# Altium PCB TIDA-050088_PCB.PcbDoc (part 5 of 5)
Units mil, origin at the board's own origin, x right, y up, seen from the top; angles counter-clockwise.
Board outline 8500 x 7000 mil, 8 copper layers (Top Layer, Layer 1 - GND, Signal Layer 2, Layer 3 - GND, Layer 4 - Power, Signal Layer 5, Layer 6 - GND, Bottom Layer), stack 61.6 mil thick; 537 components, 169 nets, 1427 pads, 1411 vias.
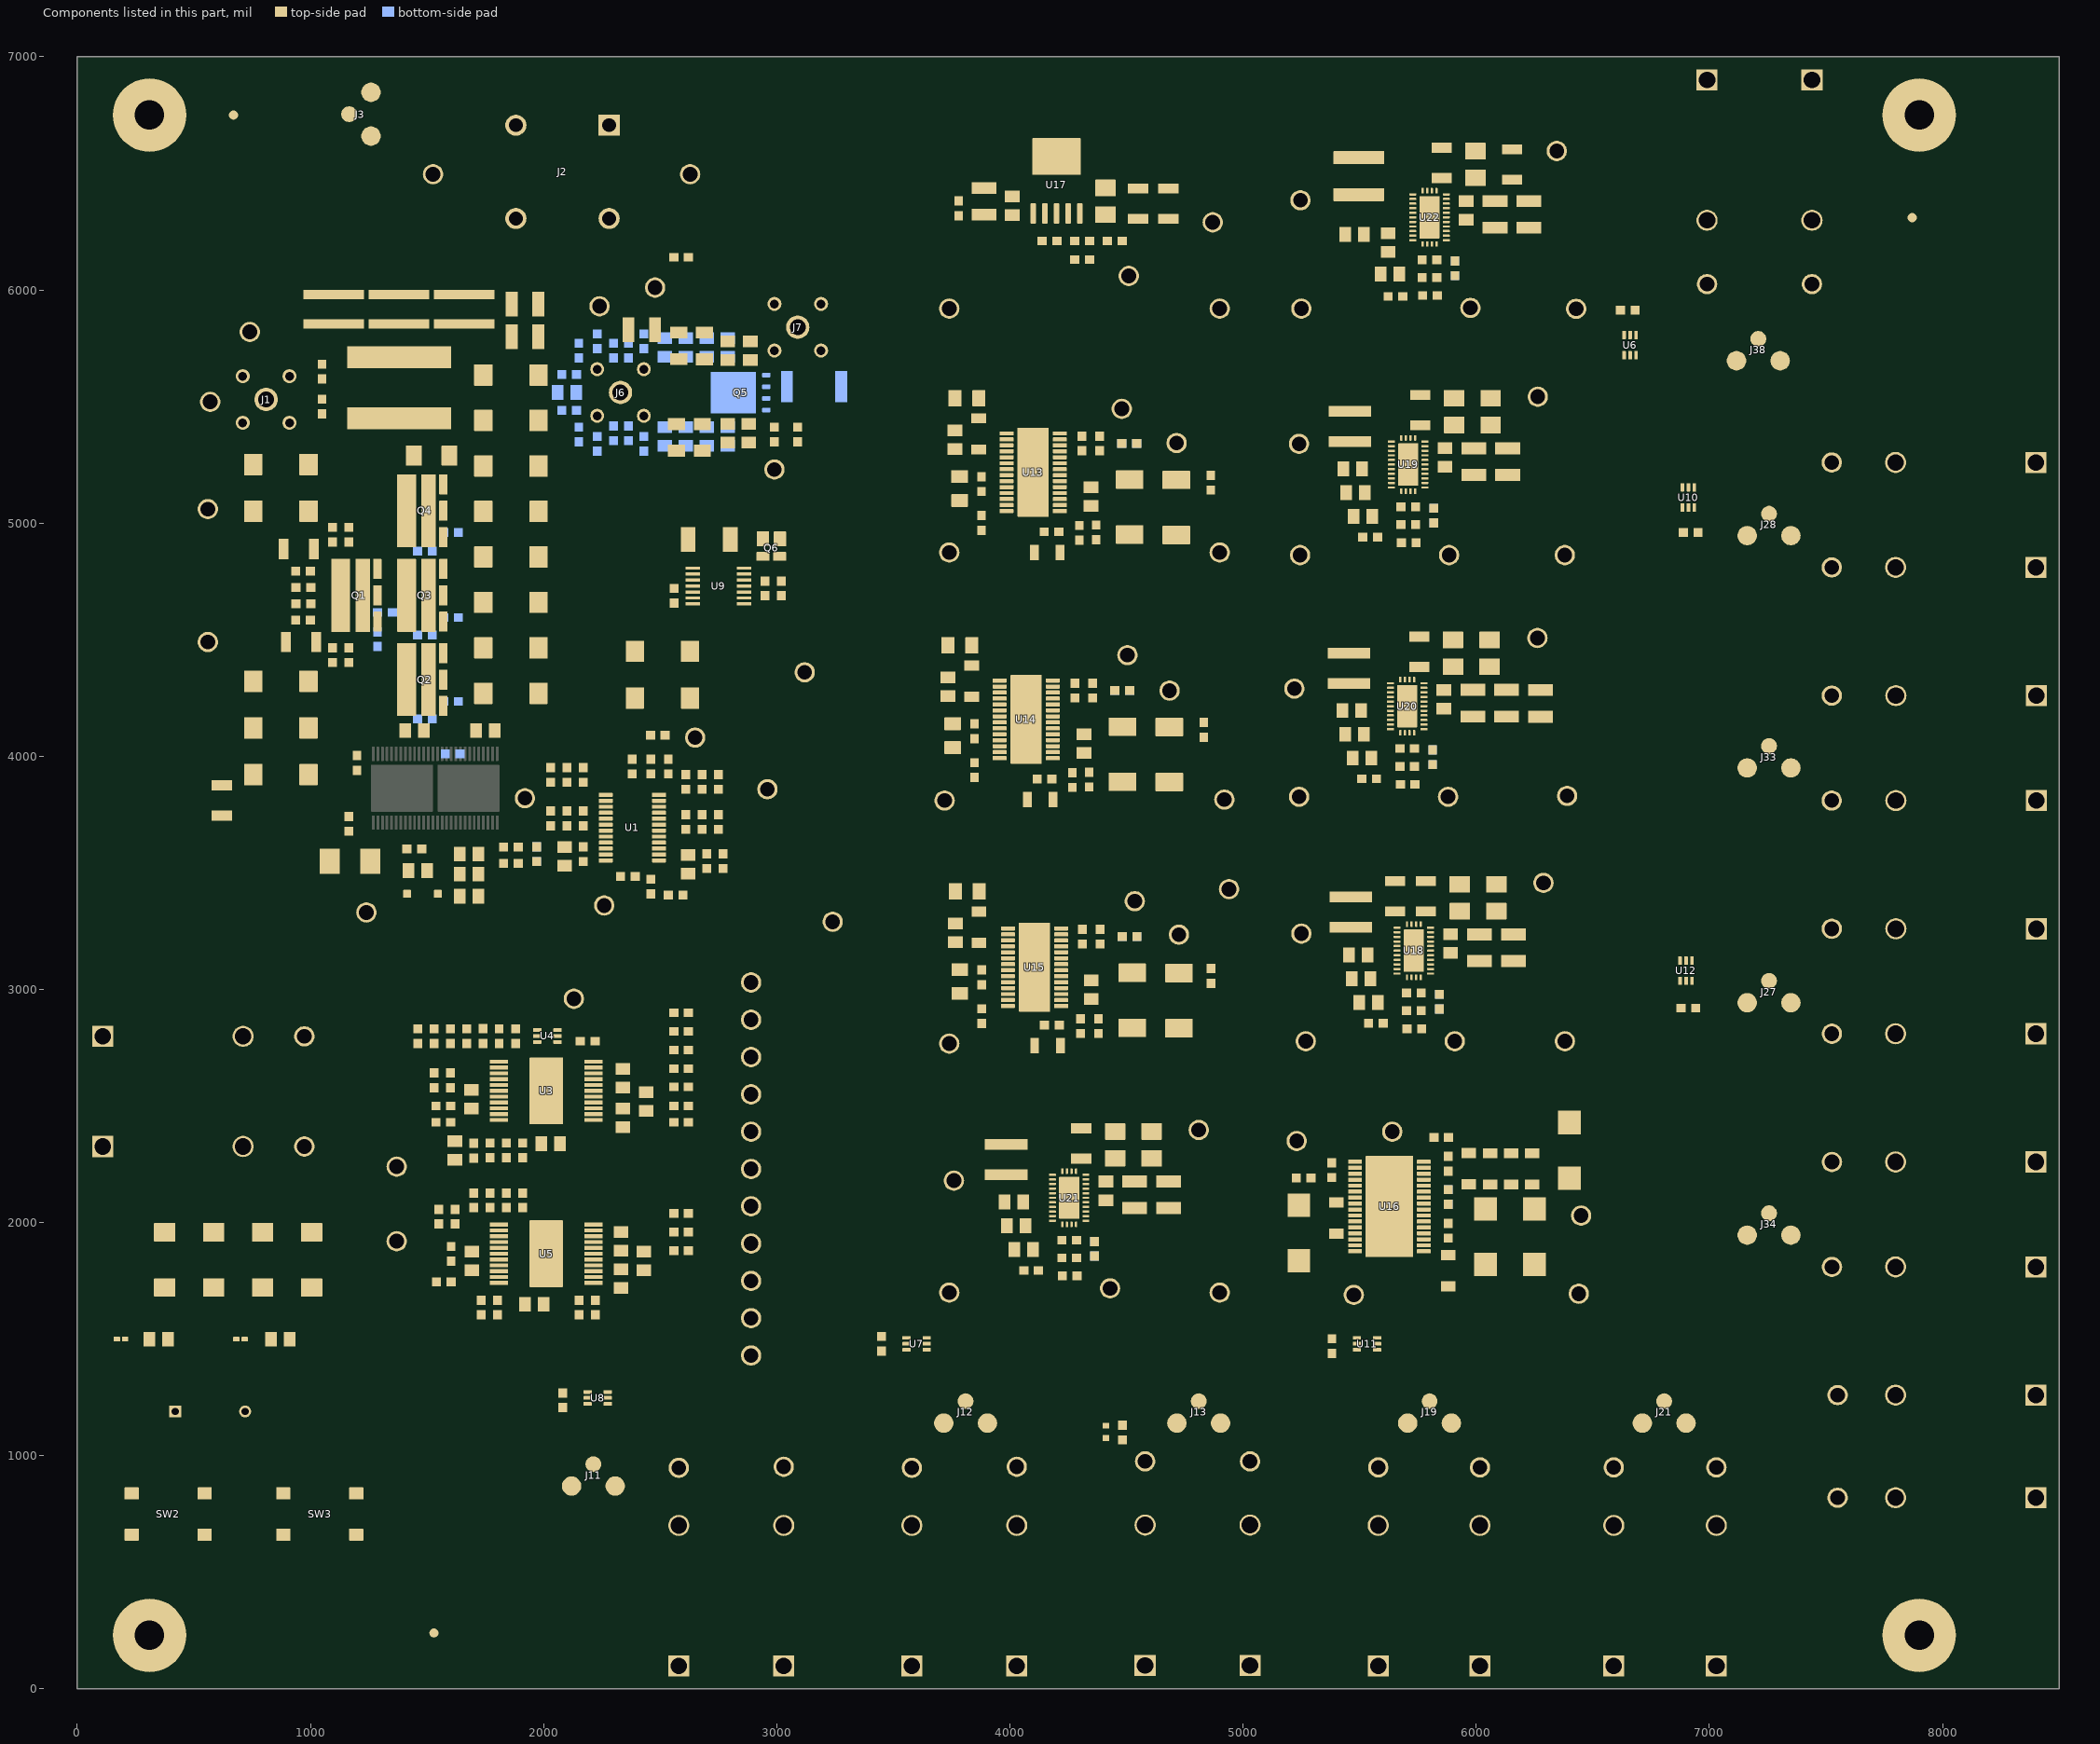
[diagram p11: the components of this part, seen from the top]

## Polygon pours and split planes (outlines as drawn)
GND on Top Layer "TOP_LAYER_GND_P095" (solid, pour order 95): 0,0 8500,0 8500,7000 0,7000
12V0_SYS on Top Layer "TOP_LAYER_12V0_SYS_P065" (solid, pour order 65): 1183.72,4445.77 1172.95,4435 1075,4435 1070,4430 1070,3650 1067.25,3650 1020,3602.75 1020,3000 1300,2748.82 1300,1906.24 1233.76,1840 320,1840 290,1870 290,2061.43 323.33,2090 1050,2090 1079.8,2119.8 1079.8,2460 1060,2480 0,2480 0,2599.91 10.55,3760.55 50,3800 725,3800 820,3895 820,4340 965,4485 965,4885.33 820,5040 820,5315 840,5335 1040,5335 1067.25,5307.75 1067.25,4952.75 1075,4945 1183.72,4945
GND on Top Layer "TOP_LAYER_GND_P050" (solid, pour order 50): 2540,5350 2530,5340 2530,5250 2540,5240 2740,5240 2760,5260 2910,5260 2920,5270 2920,5370 2910,5380 2750,5380 2720,5350 2550,5350
0V8 on Top Layer "TOP_LAYER_0V8_P061" (solid, pour order 61): 2940,5740 2440.86,5739.14 2430,5750 2430,5850 2400,5880 2400,6160 2320,6240 2180,6240 2160,6260 2160,6730 2090,6800 1160,6800 940,6580 940,5980 970,5950 1690,5950 1800,5950 1809.76,5960 1809.76,5990 1820,6000.24 1890.24,6000.24 1900.49,5990 1900.49,5720.49 1840,5660 1840,4320 1970,4190 2490,4190 2510,4210 2510,4800 2560,4850 2671.32,4850 2730,4910 2730,5020 2950,5240 2950,5730
SW_0V8 on Top Layer "TOP_LAYER_SW_0V8_P059" (solid, pour order 59): 1370,4170 1450,4170 1455,4175 1455,5205 1520,5270 1520,5340 1530,5350 1600,5350 1610,5360 1610,5500 1600,5510 1160,5510 1150,5500 1150,5170 1191.63,5128.37 1191.63,4348.37
1V5_GTY on Top Layer "TOP_LAYER_1V5_GTY_P080" (solid, pour order 80): 4182.31,5198.46 4185.6,5195.16 4403.48,5195.16 4456.09,5142.55 4792.55,5142.55 4834.94,5184.94 4881.16,5184.94 4885.1,5188.87 4885.1,5244.9 4830,5300 4830,5405 4820,5415 4590,5415 4580,5405 4580,5295 4580,5286.98 4560,5266.98 4186.59,5266.98 4182.31,5262.7
1V5 on Top Layer "TOP_LAYER_1V5_P078" (solid, pour order 78): 4152.31,4202.7 4156.59,4206.98 4509.92,4206.98 4510,4206.89 4526.89,4206.89 4550,4230 4550,4340 4560,4350 4790,4350 4800,4340 4800,4220.19 4800.69,4220.19 4810.72,4210.16 4810.99,4210.44 4840,4210.44 4840,4210 4850.6,4199.4 4850.6,4124.94 4813.32,4124.94 4770.93,4082.55 4407.45,4082.55 4354.84,4135.16 4155.6,4135.16 4152.31,4138.46
0V92 on Top Layer "TOP_LAYER_0V92_P071" (solid, pour order 71): 4185,3135 4185,3075 4188.24,3071.76 4253.24,3071.76 4255,3070 4420,3070 4475,3015 4790,3015 4845,3070 4882.03,3070 4882.03,3127.97 4850,3160 4850,3290 4840,3300 4610,3300 4600,3290 4600,3160 4585,3145 4195,3145
2V5_DDR on Top Layer "TOP_LAYER_2V5_DDR_P072" (solid, pour order 72): 3889.06,2309.27 3893.81,2304.52 4225.92,2304.52 4249.54,2328.14 4860,2328.14 4870,2338.14 4870,2516.01 4856.01,2530 4740,2530 4680,2470 4680,2469.16 3900.84,2469.16 3899.96,2470.04 3889.69,2459.77 3889.06,2459.77
3V3_VCCO on Top Layer "TOP_LAYER_3V3_VCCO_P070" (solid, pour order 70): 7137.56,6980.43 7137.56,6006.26 7071.3,5940 6860,5940 6763.36,6036.64 6763.36,6256.64 6486.85,6533.15 6210,6533.15 6210,6800 6250,6840 6610,6840 6763.36,6993.36
1V2_VCCO on Top Layer "TOP_LAYER_1V2_VCCO_P020" (solid, remove dead copper, pour order 20): 4025,3077.49 4019.29,3071.79 3919.48,3071.79 3895.66,3048.3 3885.82,3048.3 3738.04,3048.3 3730,3056.34 3730,3140 3735,3145 4020,3145 4025,3140
2V5_DDR on Top Layer "TOP_LAYER_2V5_DDR_P023" (solid, remove dead copper, pour order 23): 4016.71,5197.94 4013.96,5195.18 3914.1,5195.18 3887.4,5168.85 3751.15,5168.85 3739.34,5180.66 3739.34,5257.04 3749.28,5266.98 4013.58,5266.98 4016.71,5263.84
5V0_SYS on Top Layer "TOP_LAYER_5V0_SYS_P067" (solid, pour order 67): 4986.33,6230 5000,6243.67 5000,6340 4976.94,6363.06 4533.06,6363.06 4520,6350 4520,6240 4530,6230
BIAS_0V92 on Top Layer "TOP_LAYER_BIAS_0V92_P021" (solid, remove dead copper, pour order 21): 3730,3170.17 3734.51,3165.66 3899.45,3165.66 3905.84,3172.05 3905.84,3187.32 3918.52,3200 4019.43,3200 4022.5,3203.07 4022.5,3218.11 4020.61,3220 3738.07,3220 3730,3211.93
BIAS_1V5_GTY on Top Layer "TOP_LAYER_BIAS_1V5_GTY_P024" (solid, remove dead copper, pour order 24): 3731.21,5294.04 3732.68,5292.56 3897.62,5292.56 3904.01,5298.96 3904.01,5314.23 3913.08,5323.3 4014,5323.3 4015.72,5325.02 4015.72,5341.54 4013.9,5343.36 3732.71,5343.36 3731.21,5341.86
12V0_SYS on Top Layer "TOP_LAYER_12V0_SYS_P028" (solid, remove dead copper, pour order 28): 6288.73,6205.88 6275.2,6192.35 6001.05,6192.35 5949.73,6243.67 5940.98,6243.67 5900,6284.65 5856.37,6284.65 5853.47,6287.55 5853.47,6335.11 5857.41,6339.05 6271.57,6339.05 6288.73,6321.89
SW_3V3_VCCO on Top Layer "TOP_LAYER_SW_3V3_VCCO_P030" (solid, remove dead copper, pour order 30): 5741.8,6322.61 5742.42,6322.61 5745.31,6325.5 5745.31,6420.75 5730.27,6435.8 5367.63,6435.8 5360.23,6428.4 5360.23,6337.22 5366.96,6330.5 5541.83,6330.5 5542.31,6330.86 5555.65,6330.82 5676.74,6330.5 5684.62,6322.61
3V3_VCCO on Top Layer "TOP_LAYER_3V3_VCCO_P031" (solid, remove dead copper, pour order 31): 6479.06,6554.72 6457.49,6533.15 5795.51,6533.15 5763.52,6501.16 5377.55,6501.16 5360.23,6518.48 5360.23,6653.7 5368.59,6662.06 6456.53,6662.06 6479.06,6639.53
12V0_SYS on Top Layer "TOP_LAYER_12V0_SYS_P033" (solid, remove dead copper, pour order 33): 6221.6,3061.2 6206.56,3046.15 5935.01,3046.15 5882.6,3098.55 5873.85,3098.55 5832.87,3139.53 5789.24,3139.53 5786.34,3142.43 5786.34,3189.99 5790.28,3193.93 6204.44,3193.93 6221.6,3176.77
SW_1V2 on Top Layer "TOP_LAYER_SW_1V2_P034" (solid, remove dead copper, pour order 34): 5674.67,3177.49 5675.29,3177.49 5678.18,3180.38 5678.18,3275.64 5663.14,3290.68 5370.68,3290.68 5365,3285 5365,3190.91 5370.53,3185.38 5474.71,3185.38 5475.18,3185.74 5488.52,3185.71 5609.61,3185.38 5617.49,3177.49
1V2 on Top Layer "TOP_LAYER_1V2_P035" (solid, remove dead copper, pour order 35): 6411.94,3508.19 6411.94,3401.77 6398.2,3388.03 5729.98,3388.03 5704.35,3364.41 5372.24,3364.41 5367.49,3369.16 5367.49,3519.66 5378.39,3529.93 6391.96,3528.16
12V0_SYS on Top Layer "TOP_LAYER_12V0_SYS_P036" (solid, remove dead copper, pour order 36): 6197.31,5146.1 6182.27,5131.05 5910.72,5131.05 5858.32,5183.45 5849.56,5183.45 5808.59,5224.43 5764.96,5224.43 5762.05,5227.33 5762.05,5274.9 5765.99,5278.83 6180.16,5278.83 6197.32,5261.67
SW_1V2_VCCO on Top Layer "TOP_LAYER_SW_1V2_VCCO_P037" (solid, remove dead copper, pour order 37): 5650.38,5262.39 5651.01,5262.39 5653.89,5265.28 5653.89,5360.54 5638.85,5375.58 5367.72,5375.58 5360.76,5368.62 5360.76,5286.85 5377.33,5270.28 5450.42,5270.28 5450.9,5270.64 5464.23,5270.61 5585.32,5270.28 5593.21,5262.39
1V2_VCCO on Top Layer "TOP_LAYER_1V2_VCCO_P038" (solid, remove dead copper, pour order 38): 6387.65,5587.35 6387.65,5492.65 6367.93,5472.93 5705.69,5472.93 5680.06,5449.31 5371.66,5449.31 5364.24,5456.73 5364.24,5595.52 5384.68,5614.78 6361.93,5613.07
12V0_SYS on Top Layer "TOP_LAYER_12V0_SYS_P039" (solid, remove dead copper, pour order 39): 6337.82,4105.88 6326.54,4094.6 5906.37,4094.6 5853.97,4147 5845.22,4147 5804.24,4187.98 5760.61,4187.98 5757.71,4190.88 5757.71,4238.44 5761.64,4242.38 6326.31,4242.38 6337.82,4230.87
SW_1V2_MEM on Top Layer "TOP_LAYER_SW_1V2_MEM_P040" (solid, remove dead copper, pour order 40): 5646.04,4225.94 5646.66,4225.94 5649.55,4228.83 5649.55,4324.09 5634.5,4339.13 5363.37,4339.13 5356.41,4332.17 5356.41,4242.56 5365.14,4233.83 5446.07,4233.83 5446.55,4234.19 5459.88,4234.16 5580.97,4233.83 5588.86,4225.94
1V2_MEM on Top Layer "TOP_LAYER_1V2_MEM_P041" (solid, remove dead copper, pour order 41): 6383.3,4551.7 6383.3,4458.3 6361.48,4436.48 5701.35,4436.48 5675.71,4412.86 5367.31,4412.86 5359.89,4420.28 5359.89,4560.96 5378.33,4578.33 6358.38,4576.62
12V0_SYS on Top Layer "TOP_LAYER_12V0_SYS_P042" (solid, remove dead copper, pour order 42): 4743.17,2001.31 4728.13,1986.26 4456.58,1986.26 4404.17,2038.66 4395.42,2038.66 4354.44,2079.64 4310.81,2079.64 4307.91,2082.54 4307.91,2130.1 4311.85,2134.04 4726.01,2134.04 4743.17,2116.88
SW_2V5_DDR on Top Layer "TOP_LAYER_SW_2V5_DDR_P043" (solid, remove dead copper, pour order 43): 4196.24,2117.6 4196.86,2117.6 4199.75,2120.49 4199.75,2215.75 4184.71,2230.79 3890.79,2230.79 3885,2225 3885,2135 3894.51,2125.49 3996.28,2125.49 3996.75,2125.85 4010.09,2125.82 4131.18,2125.49 4139.06,2117.6
2V5_DDR on Top Layer "TOP_LAYER_2V5_DDR_P046" (solid, remove dead copper, pour order 46): 3986.71,4137.94 3983.96,4135.18 3884.1,4135.18 3863.84,4115.2 3854,4115.2 3702.51,4115.2 3695,4122.71 3695,4197.4 3704.58,4206.98 3983.58,4206.98 3986.71,4203.84
BIAS_1V5 on Top Layer "TOP_LAYER_BIAS_1V5_P047" (solid, remove dead copper, pour order 47): 3701.21,4234.04 3702.68,4232.56 3867.62,4232.56 3874.01,4238.96 3874.01,4254.23 3883.08,4263.3 3984,4263.3 3985.72,4265.02 3985.72,4281.54 3983.9,4283.36 3702.71,4283.36 3701.21,4281.86
GND_0V8 on Top Layer "TOP_LAYER_GND_0V8_P062" (solid, pour order 62): 1995,3979.68 1995,3480 2260,3480 2295,3445 2805,3445 2820,3460 2820,4020 2760,4080 2615,4080 2610,4075 2560,4125 2360.4,4125 2285.4,4050 2010.12,4050 1995.12,4035 1993.86,4035
GND_0V8 on Layer 1 - GND "LAYER_1_-_GND_GND_0V8_P060" (solid, pour order 60): 1995,3979.68 1995,3480 2260,3480 2295,3445 2805,3445 2820,3460 2820,4020 2760,4080 2615,4080 2610,4075 2560,4125 2360.4,4125 2285.4,4050 2010.12,4050 1995.12,4035 1993.86,4035
GND on Layer 1 - GND "LAYER_1_-_GND_GND_P086" (solid, pour order 86): -500,0 8500,0 8500,7000 3190,7000 -500,7000
GND on Layer 3 - GND "LAYER_3_-_GND_GND_P055" (solid, pour order 55): -500,-8.15 8500,-8.15 8500,6991.85 3190,6991.85 -500,6991.85
5V0_SYS on Layer 4 - Power "LAYER_4_-_POWER_5V0_SYS_P081" (solid, pour order 81): 4740,6212.92 4715.25,6237.67 4715,6237.67 4715,6995 4720,7000 6600,7000 6600,6450 6570,6420 5090.1,6420 5030,6359.9 5030,6237.67 5000,6212.92 4990,6212.92
5V0_SYS on Layer 4 - Power "LAYER_4_-_POWER_5V0_SYS_P082" (solid, pour order 82): 1983.99,0 1983.99,1332.09 2184.04,1332.09 2200,1350 2200,1580 6360,1580 6360,7000 8500,7000 8500,0
12V0_SYS on Layer 4 - Power "LAYER_4_-_POWER_12V0_SYS_P083" (solid, pour order 83): 0,6990 0,0 2190,0 2190,1590 6340,1590 6340,6990 3400,6990
GND on Layer 6 - GND "LAYER_6_-_GND_GND_P052" (solid, pour order 52): 0,0 8500,0 8500,7000 3190,7000 0,7000
0V8 on Bottom Layer "BOTTOM_LAYER_0V8_P096" (solid, pour order 96): 1860,5000 1840.91,5019.09 1840.91,5660.91 1840.91,5708.78 1829.91,5719.79 1829.91,5760.03 1829.91,5940.09 1820,5950 950,5950 940,5960 940,6530 980,6570 1565.96,6570 1795.96,6800 2050,6800 2110,6740 2110,6307.31 2178.22,6239.09 2323.01,6239.09 2401.19,6160.9 2401.19,5881.19 2375.24,5855.24 2136.63,5855.24 2120,5838.61 2120,5750 2130,5740 2120,5700 2110,5690 2100,5700 2030,5700 2010,5680 2010,5390 2010,5440 2030,5420 2100,5420 2110,5430 2130,5430 2130,5380 2120,5370 2120,5020 2100,5000
GND on Bottom Layer "BOTTOM_LAYER_GND_P085" (solid, pour order 85): 2100,5440 2090,5430 2030,5430 2020,5440 2020,5680 2030,5690 2090,5690 2100,5680
0V8 on Bottom Layer "BOTTOM_LAYER_0V8_P093" (solid, pour order 93): 2110,5730 2120,5740 2180,5740 2190,5750 2190,5770 2200,5780 2260,5780 2270,5770 2270,5750 2280,5740 2390,5740 2400,5750 2400,5770 2410,5780 2451.5,5780 2460,5771.5 2460,5760 2470,5750 2890,5750 2913.23,5726.77 2913.23,5389.88 2903.35,5380 2890,5380 2470,5380 2460,5370 2460,5350 2450,5340 2410,5340 2400,5350 2400,5380 2395,5385 2275,5385 2270,5380 2270,5350 2260,5340 2200,5340 2190,5350 2190,5370 2180,5380 2110,5380 2110,5400
GND on Bottom Layer "BOTTOM_LAYER_GND_P097" (solid, pour order 97): 35,15 60,-10 8485,-10 8485,6980 8425,7040 -5,7040
2V5_DDR on Bottom Layer "BOTTOM_LAYER_2V5_DDR_P079" (solid, pour order 79): 4700,2330 4690,2340 4690,2470 4750,2530 4860,2530 4880,2510 4880,2350 4860,2330
1V5_GTY on Bottom Layer "BOTTOM_LAYER_1V5_GTY_P077" (solid, pour order 77): 4580,5405 4590,5415 4820,5415 4830,5405 4830,5295 4820,5285 4590,5285 4580,5295
1V5 on Bottom Layer "BOTTOM_LAYER_1V5_P074" (solid, pour order 74): 4550,4340 4560,4350 4790,4350 4800,4340 4800,4230 4790,4220 4560,4220 4550,4230
GND on Signal Layer 5 "SIGNAL_LAYER_5_GND_P092" (solid, pour order 92): 0,7000 8500,7000 8500,0 0,0
3V3_VCCO on Signal Layer 5 "SIGNAL_LAYER_5_3V3_VCCO_P084" (solid, pour order 84): 6550,7000 6550,1590 3640,1590 3640,7000
GND on Signal Layer 2 "SIGNAL_LAYER_2_GND_P091" (solid, pour order 91): 0,0 8490,0 8500,10 8500,7000 0,7000

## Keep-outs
Keep-Out Layer:
  text ".Layer_Name" at 577,-858.49 h60

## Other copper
Top Layer:
  region net 1V2_MEM: 5512.01,2072.01 5515,2075 5515,2115 5512.61,2117.39 5337.61,2117.39 5315,2140 5189.9,2140 5180,2130.1 5180,2025 5190,2015 5325,2015 5365,2055 5430,2055 5447.01,2072.01
  region net 0V6_VTT: 5745,2115 5747.39,2117.39 5807.61,2117.39 5815,2110 5897.5,2110 5925,2137.5 5925,2185 5930,2190 6285,2190 6340,2245 6440,2245 6515,2245 6525,2235 6525,2015 6525,1902.5 6500,1870 6390,1870 6350,1910 6350,1995 6340,2005 5985,2005 5965,2025 5825,2025 5820,2020 5748.73,2020 5745,2023.73 5745,2025
  region net BP5H_0V8: 1380.83,4141.5 1380.83,3979.84 1432.01,3979.84 1432.01,4141.5
  region net SW_0V8: 1439.88,3960 1439.88,4042.15 1450,4053.22 1450,4160 1510.75,4160 1510.75,3960
  region net HOH_0V8: 1321.77,4135 1321.77,3979.84 1372.96,3979.84 1372.96,4135
  region net HOL_0V8: 1262.72,4135 1262.72,3979.84 1313.9,3979.84 1313.9,4135
  region net LOL_0V8: 1557.99,4135.16 1557.99,3980 1609.18,3980 1609.18,4135.16
  region net LOH_0V8: 1617.05,4135.16 1617.05,3980 1668.23,3980 1668.23,4135.16
  region net BP5L_0V8: 1676.11,4141.34 1676.11,3979.68 1727.29,3979.68 1727.29,4141.34
  region net NetL1_2: 1150,5650 1130,5670 1130,5770 970,5830 970,5890 1000,5920 1760,5920 1790,5890 1790,5830 1630,5770 1630,5670 1610,5650
  region net SW_0V8: 1420,3680 1420,3739.87 1420,3770 1510,3770 1510.75,3769.25 1510.75,3671.2 1510.75,3635.17 1496.44,3620.86 1457.6,3620.86 1457.6,3632.4 1420,3670
  text ".Layer_Name" at 577,-858.49 h60
Bottom Layer:
  region net NetJ7_1: 3059.85,5510 3069.85,5520 3069.85,5650 3059.85,5660 2929.85,5660 2919.85,5650 2919.85,5530.3 2919.85,5520 2929.85,5510 2940.15,5510
  region net HOL_0V8: 1313.9,4045 1313.9,4135.16 1262.72,4135.16 1262.72,4045
  region net LOH_0V8: 1630.14,4045 1625.14,4050 1625.14,4140 1660.14,4140 1660.14,4050 1655.14,4045
  region net NetQ1_1: 1268.75,4518.8 1307.83,4518.8 1307.82,4631.2 1268.75,4631.2
  region net HOH_0V8: 1335,4045 1330,4050 1330,4140 1365,4140 1365,4050 1360,4045
  region net NetQ2_1: 1552.24,4141.65 1591.61,4141.65 1591.61,4254.05 1552.24,4254.05
  region net NetQ3_1: 1551.81,4502.44 1591.18,4502.44 1591.18,4614.84 1551.81,4614.84
  region net NetQ4_1: 1550.31,4860.98 1589.69,4860.98 1589.69,4973.38 1550.32,4973.38
  region net LOL_0V8: 1505,4045 1450,4100 1450,4135 1601.09,4135 1601.09,4050 1596.09,4045
  text ".Layer_Name" at 577,-858.49 h60

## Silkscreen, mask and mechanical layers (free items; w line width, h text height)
Top Overlay:
  drawing of 472 lines, arcs and shapes, not listed
  text "2" at 5333.77,6734.99 h40
  text "5V0_SYS @ 50mA" at 4030,6725.04 h80
  text "3V3_VCCO @ 6A" at 5550,6725.1 h80
  text "3.28cm" at 5159.49,6708.08 h60
  text "2" at 4963.77,6544.99 h40
  text "1.91cm" at 4789.49,6518.08 h60
  text "0V80 @ 44A" at 1857.33,6119.09 h75
  text "2" at 903.77,6089.99 h40
  text "21.9cm" at 729.44,6063.08 h60
  text "2" at 6715.58,6039.89 h40
  text "Load Step" at 2558.5,6024.21 h80
  text "0.23cm" at 6541.3,6012.98 h60
  text "1V5_GTY @ 0.2A" at 4050,5675.1 h80
  text "1V2_VCCO @ 4A" at 5540,5675.1 h80
  text "2" at 5323.77,5664.99 h40
  text "3.05cm" at 5149.49,5638.08 h60
  text "3V3_VCCO @ 6A" at 6898.85,5558.87 h90
  text "2" at 4123.77,5514.99 h40
  text "3.45cm" at 3949.49,5488.08 h60
  text "2" at 6823.77,5256.17 h40
  text "0.23cm" at 6649.49,5229.27 h60
  text "0V8 (VCCINT) @ 44A" at 335.05,5210 h80 r270
  text "Discharge" at 2700,5035.02 h80
  text "1V2_VCCO @ 2A" at 7063.05,4721.55 h90 r90
  text "1V2_MEM @ 6A" at 5570,4635.1 h80
  text "1V5 @ 1.5A" at 4140,4625.1 h80
  text "2" at 5323.77,4624.99 h40
  text "2" at 3229.96,4600 h40
  text "3.19cm" at 5149.49,4598.08 h60
  text "1.30cm" at 3060,4570.65 h60
  text "2" at 4093.77,4454.99 h40
  text "3.45cm" at 3919.49,4428.08 h60
  text "U2" at 1200.54,3880 h50 r270
  text "1V2_MEM @ 6A" at 7063.05,3743.94 h90 r90
  text "1V2 @ 2A" at 5670,3585.1 h80
  text "0V92 @ 1A" at 4150,3575.1 h80
  text "2" at 5333.77,3574.99 h40
  text "3.05cm" at 5159.49,3548.08 h60
  text "2" at 4123.77,3404.99 h40
  text "3.45cm" at 3949.49,3378.08 h60
  text "2" at 6813.77,3216.17 h40
  text "0.23cm" at 6639.49,3189.27 h60
  text "12V0_SYS @ 7A" at 1100,3073.5 h80 r270
  text "Sequencing" at 1220,3050 h80
  text "1V2 @ 2A" at 7063.05,2855.28 h90 r90
  text "2V5_DDR @ 3A" at 4069.93,2525.1 h80
  text "2" at 3853.77,2514.99 h40
  text "0V6_VTT @ 3A, 0V6_VTTREF @ 10mA" at 5130,2510 h80
  text "3.05cm" at 3679.49,2488.08 h60
  text "2" at 2333.77,2224.99 h40
  text "6.21cm" at 2159.49,2198.08 h60
  text "2" at 5783.77,1774.99 h40
  text "2V5_DDR @ 0.1A" at 7064.9,1749.99 h80 r90
  text "4.48cm" at 5609.49,1748.08 h60
  text "2" at 3860.97,1566.39 h40
  text "2" at 5803.77,1566.17 h40
  text "0.23cm" at 5629.49,1539.27 h60
  text "0.23cm" at 3690.41,1538.07 h60
  text "1V5 @ 1.5A" at 3676.74,1416.95 h90
  text "1V5_SMON @ 0.4A" at 4447.97,1416.95 h90
  text "0V92 @ 1A" at 5613.72,1416.95 h90
  text "0V6_VTT @ ±3A" at 6507.07,1416.95 h90
  text "SYS Power" at 95.03,1370 h70
  text "SEQ UP DONE" at 597.74,1370 h70
  text "2" at 2509.92,1313.44 h40
  text "0.23cm" at 2335.64,1286.53 h60
  text "Enable" at 230,1180 h50
  text "Disable" at 770,1180 h50
  text "1V5_GTY @ 0.2A" at 2341.59,1166.95 h90
  text "SEQUENCER DISABLE" at 245,1010 h70
  text "0V6_VTTREF @ ±10mA" at 7369.9,644.32 h80 r90
  text "SEQUENCE UP" at 90,510 h70
  text "SEQUENCE DOWN" at 740,510 h70
  text "TIDA-050088 - Rev A" at 600,100 h80
  text ".Layer_Name" at 577,-858.49 h60
Bottom Overlay:
  text ".Layer_Name" at 577,-858.49 h60
Top Paste:
  region: 1732.42,3799.81 1551.31,3799.81 1550.92,3799.81 1550.2,3800.11 1549.64,3800.66 1549.35,3801.39 1549.35,3801.78 1549.35,3923.83 1549.35,3924.22 1549.64,3924.94 1550.2,3925.5 1550.92,3925.79 1551.31,3925.79 1732.42,3925.79 1732.81,3925.79 1733.53,3925.5 1734.08,3924.94 1734.38,3924.22 1734.38,3923.83 1734.38,3801.78 1734.38,3801.39 1734.08,3800.66 1733.53,3800.11 1732.81,3799.81 1732.42,3799.81
  region: 1335.96,3801.78 1335.96,3923.83 1335.96,3924.22 1336.26,3924.94 1336.81,3925.5 1337.54,3925.79 1337.93,3925.79 1519.03,3925.79 1519.42,3925.79 1520.15,3925.5 1520.7,3924.94 1521,3924.22 1521,3923.83 1521,3801.78 1521,3801.39 1520.7,3800.66 1520.15,3800.11 1519.42,3799.81 1519.03,3799.81 1337.93,3799.81 1337.54,3799.81 1336.81,3800.11 1336.26,3800.66 1335.96,3801.39 1335.96,3801.78
  text ".Layer_Name" at 577,-858.49 h60
Bottom Paste:
  text ".Layer_Name" at 577,-858.49 h60
Top Solder:
  region: 1732.42,3799.81 1551.31,3799.81 1550.92,3799.81 1550.2,3800.11 1549.64,3800.66 1549.35,3801.39 1549.35,3801.78 1549.35,3923.83 1549.35,3924.22 1549.64,3924.94 1550.2,3925.5 1550.92,3925.79 1551.31,3925.79 1732.42,3925.79 1732.81,3925.79 1733.53,3925.5 1734.08,3924.94 1734.38,3924.22 1734.38,3923.83 1734.38,3801.78 1734.38,3801.39 1734.08,3800.66 1733.53,3800.11 1732.81,3799.81 1732.42,3799.81
  region: 1335.96,3801.78 1335.96,3923.83 1335.96,3924.22 1336.26,3924.94 1336.81,3925.5 1337.54,3925.79 1337.93,3925.79 1519.03,3925.79 1519.42,3925.79 1520.15,3925.5 1520.7,3924.94 1521,3924.22 1521,3923.83 1521,3801.78 1521,3801.39 1520.7,3800.66 1520.15,3800.11 1519.42,3799.81 1519.03,3799.81 1337.93,3799.81 1337.54,3799.81 1336.81,3800.11 1336.26,3800.66 1335.96,3801.39 1335.96,3801.78
  text ".Layer_Name" at 577,-858.49 h60
  text ".Layer_Name" at 577,-858.49 h60
Bottom Solder:
  text ".Layer_Name" at 577,-858.49 h60
Drill Guide:
  text ".Layer_Name" at 577,-858.49 h60
M1 Board Outline:
  the board outline again, w10
  text ".Layer_Name" at 577,-858.49 h60
M2 Board Dimensions:
  rectangle: 0,-275 125,-150
  rectangle: 125,-400 500,-275
  lines w7: 0,-275 1000,-275 ; 125,-400 125,-150 ; 250,-400 250,-150 ; 500,-400 500,-150 ; 750,-400 750,-150 ; 0,-400 1000,-400 1000,-150 0,-150 0,-400
  text ".Layer_Name" at 577,-858.49 h60
M3 3D STEP Top:
  text ".Layer_Name" at 577,-858.49 h60
M4 3D STEP Bottom:
  text ".Layer_Name" at 577,-858.49 h60
M5 Assembly Top:
  lines w5.91: 1257.61,3740.76 1812.73,3740.76 1812.73,3984.85 1257.61,3984.85 1257.61,3740.76
  lines w10: -292,-930.17 6308,-930.17 ; -292,-726.83 6310,-726.83 ; -292,-523.5 -292,-1133.5 3713,-1133.5 6310,-1133.5 6310,-523.5 -291.5,-523.5 -291.5,-1133.5 1284,-1133.5 ; 2173,-1133.5 2173,-523.5 ; 3440,-726.83 3440,-523.5 ; 4280,-726.83 4280,-523.5 ; 4902,-1140 4902,-937.17
  text ".Designator" at 1535.17,3862.8 h19.68 r90
  text "COMPONENTS MARKED 'DNP' SHOULD NOT BE POPULATED." at 1153.5,-318.5 h60
  text "ASSEMBLY VARIANT:" at 1153,-434 h60
  text ".VariantName" at 2189,-434 h60
  text "PCB VIEWED FROM TOP SIDE" at -228.5,-655.67 h60
  text "BOARD #:" at 2248,-655.67 h60
  text ".PRJ_Number" at 2793.5,-655.67 h60
  text "REV:" at 3638,-655.67 h60
  text ".PCB_Rev" at 3929.5,-655.67 h60
  text "SVN REV:" at 4476,-655.67 h60
  text ".VersionControl_RevNumber" at 4982,-655.67 h60
  text "TID #:" at 2248,-859 h60
  text ".TID" at 2793.5,-859 h60
  text "PLOT NAME =" at -228.5,-1064.33 h60
  text ".plot_File_Name" at 577,-1064.33 h60
  text "GENERATED    :" at 2250,-1064.33 h60
  text ".Print_Date" at 3119.5,-1064.33 h60
  text ".Print_Time" at 3848.5,-1064.33 h60
  text "TEXAS INSTRUMENTS" at 5113,-1064.33 h60
M6 Assembly Bottom:
  lines w10: -292.5,-727.33 6309.5,-727.33 ; -290.5,-930.67 6309.5,-930.67 ; 1115.5,-1140.5 1115.5,-937.67 ; 1737.5,-727.33 1737.5,-524 ; 2577.5,-727.33 2577.5,-524 ; 3844.5,-1134 3844.5,-524 ; 4733.5,-1134 6309,-1134 6309,-524 -292.5,-524 -292.5,-1134 2304.5,-1134 6309.5,-1134 6309.5,-524
  text "COMPONENTS MARKED 'DNP' SHOULD NOT BE POPULATED." at 6102,-318 h60
  text ".VariantName" at 5058,-434 h60
  text "ASSEMBLY VARIANT:" at 6097,-434 h60
  text ".VersionControl_RevNumber" at 1035.5,-656.17 h60
  text "SVN REV:" at 1541.5,-656.17 h60
  text ".PCB_Rev" at 2088,-656.17 h60
  text "REV:" at 2379.5,-656.17 h60
  text ".PRJ_Number" at 3224,-656.17 h60
  text "BOARD #:" at 3769.5,-656.17 h60
  text "PCB VIEWED FROM BOTTOM SIDE" at 6246,-656.17 h60
  text ".TID" at 3224,-859.5 h60
  text "TID #:" at 3769.5,-859.5 h60
  text "TEXAS INSTRUMENTS" at 904.5,-1064.83 h60
  text ".Print_Time" at 2169,-1064.83 h60
  text ".Print_Date" at 2898,-1064.83 h60
  text "GENERATED    :" at 3767.5,-1064.83 h60
  text ".plot_File_Name" at 5440.5,-1064.83 h60
  text "PLOT NAME =" at 6246,-1064.83 h60
M9 Title Sheet:
  drawing of 57 lines, arcs and shapes, not listed
  text "1" at 739.84,8036.5 h70
  text "2" at 3235.5,8036.5 h70
  text "3" at 5724.84,8036.5 h70
  text "4" at 8231.51,8036.5 h70
  text "5" at 10730.5,8036.5 h70
  text "6" at 13235.5,8036.5 h70
  text "A" at -416.5,6893.5 h70
  text "A" at 14383.5,6893.5 h70
  text "B" at -416.5,4513.5 h70
  text "B" at 14383.5,4513.5 h70
  text "C" at -416.5,2138.5 h70
  text "C" at 14383.5,2138.5 h70
  text "PROJECT TITLE:" at 11343.5,277.5 h45
  text ".PRJ_Title" at 11393.5,144.17 h70
  text "DESIGNED FOR:" at 11343.5,-23.5 h45
  text ".PRJ_Customer" at 11393.5,-163.5 h70
  text "D" at -416.5,-231.5 h70
  text "D" at 14383.5,-231.5 h70
  text "FILE NAME:" at 11343.5,-323.5 h45
  text ".PCB_File_Name_No_Path" at 11393.5,-443.5 h70
  text "Texas Instruments (TI) and/or its licensors do not warrant the accuracy or completeness of this specification" at 6374,-605.34 h45
  text "ENGINEER:" at 11343.5,-613.5 h45
  text "LAYOUT BY:" at 12848.5,-613.5 h45
  text "or any information contained therein. TI and/or its licensors do not warrant that this design will meet" at 6329.02,-718 h45
  text ".PRJ_Engineer" at 11393.5,-768.49 h70
  text ".PCB_Layout" at 12899,-768.49 h70
  text "the specifications, will be suitable for your application or fit for any particular purpose, or will operate in" at 6329.02,-830.67 h45
  text ".Layer_Name" at 577,-858.49 h60
  text "ALTIUM DESIGNER VERSION:" at 12848.5,-923.5 h45
  text "an implementation. TI and/or its licensors do not warrant that the design is production worthy. You should" at 6329.02,-943.33 h45
  text "completely validate and test your design implementation to confirm the system functionality for your application." at 6374,-1056 h45
  text ".print_Scale" at 11393.5,-1056.83 h70
  text ".Application_BuildNumber" at 12899,-1056.83 h70
  text "1" at 739.84,-1263.5 h70
  text "2" at 3235.5,-1263.5 h70
  text "3" at 5724.84,-1263.5 h70
  text "4" at 8231.51,-1263.5 h70
  text "5" at 10730.5,-1263.5 h70
  text "6" at 13235.5,-1263.5 h70
M10 Fab Notes:
  drawing of 189 lines, arcs and shapes, not listed
  text "DESIGN INFORMATION" at 12382.02,6356.18 h60
  text "MIN. TRACK WIDTH:" at 11737.46,6224.05 h60
  text "8" at 12833.7,6224.05 h60
  text "MIL" at 12988.46,6224.05 h60
  text "7.874" at 12667.32,6102.36 h60
  text "MIN. CLEARANCE:" at 11737.46,6099.92 h60
  text "MIL" at 12988.46,6099.92 h60
  text "MIN. VIA PAD SIZE:" at 11737.46,5975.8 h60
  text "24" at 12803.71,5975.8 h60
  text "MIL" at 12988.46,5975.8 h60
  text "0.05mm (2MIL)" at 12432.46,5845.9 h60
  text "MINIMUM ANNULAR RING" at 11408.23,5837.68 h60
  text "EXTERNAL" at 13140.46,5837.68 h60
  text "PER" at 11608.23,5727.55 h60
  text "IPC-D-275 CLASS 2 LEVEL C" at 11828.23,5727.55 h60
  text "MIL, HOLES" at 13316.46,5627.07 h60
  text "+/-" at 12924,5618.48 h60
  text "+/-" at 13778,5618.48 h60
  text "REGISTRATION TOLERANCES:" at 11408.23,5617.42 h60
  text "METAL" at 12608,5617.42 h60
  text "5" at 13184.2,5617.42 h60
  text "3" at 14017.2,5617.42 h60
  text "MIL" at 14133.46,5617.42 h60
  text "HOLE SIZE TOLERANCE (UNLESS OTHERWISE SPECIFIED):" at 11408.23,5519.1 h60
  text "+/-" at 13778,5516.23 h60
  text "3" at 14017.2,5515.17 h60
  text "MIL" at 14133.46,5515.17 h60
  text "MATERIAL:" at 11333.46,5377.52 h60
  text "FR-4 High Tg" at 12319.9,5249 h60
  text "X" at 12175.47,5241.01 h60
  text "FR-4" at 11754.46,5236.49 h60
  text "OTHER" at 13242.46,5236.49 h60
  text "62 MIL (1.6mm) +/-10%" at 12074.56,5093.46 h60
  text "X" at 11954.47,5091.01 h60
  text "THICKNESS:" at 11408.23,5085.24 h60
  text "OTHER" at 13359.46,5085.24 h60
  text "TOLERANCE:" at 11408.23,4946.92 h60
  text "X" at 12256.47,4946.92 h60
  text "ANSI IPC-6012 TYPE 3 CLASS 2" at 12434.48,4946.92 h60
  text "OTHER +/-" at 12434.46,4802.73 h60
  text "BOW & TWIST:" at 11408.23,4657.55 h60
  text "X" at 12256.47,4657.55 h60
  text "ANSI IPC-6012 TYPE 3 CLASS 2" at 12434.48,4657.55 h60
  text "OTHER +/-" at 12434.46,4510.85 h60
  text "DRILLING:" at 11333.46,4380.23 h60
  text "NC_DRILL FILES" at 13094.46,4275.04 h60
  text "REFERENCE:" at 11408.23,4271.1 h60
  text "X" at 12065.47,4271.01 h60
  text "AS SHOWN" at 12243.46,4271.1 h60
  text "X" at 12966.47,4271.1 h60
  text "OTHER" at 13392.46,4128.85 h60
  text "PTH COPPER THICKNESS:" at 11407.91,4125.32 h60
  text "X" at 12547.14,4125.32 h60
  text "20-30 um" at 12675.14,4125.32 h60
  text "BOARD FINISH:" at 11333.46,3977.73 h60
  text "SILKSCREEN:" at 11488.68,3867.6 h60
  text "X" at 12446.47,3867.6 h60
  text "TOP" at 12563.46,3867.6 h60
  text "X" at 12956.47,3867.6 h60
  text "BOTTOM" at 13074.46,3867.6 h60
  text "SILKSCREEN COLOR:" at 11488.68,3712.41 h60
  text "X" at 12445.47,3712.41 h60
  text "WHITE" at 12563.46,3712.41 h60
  text "OTHER" at 13074.46,3712.41 h60
  text "X" at 12576.47,3568.96 h60
  text "GREEN" at 12694.46,3568.96 h60
  text "OTHER" at 13312.46,3568.96 h60
  text "SOLDER RESIST COLOR:" at 11488.68,3562.1 h60
  text "X" at 12576.47,3414.71 h60
  text "MATTE" at 12694.46,3414.71 h60
  text "SEMI-GLOSS" at 13312,3414.07 h60
  text "IMMERSION GOLD (ENIG)" at 12394.46,3241.94 h60
  text "ENEPIG" at 13732,3234.72 h60
  text "SURFACE FINISH:" at 11333.46,3233.72 h60
  text "X" at 12216.47,3233.72 h60
  text "IMM. TIN/SILVER OR EQUIV" at 11663,3096.4 h60
  text "OTHER" at 13094.46,3092.47 h60
  text "ARRAY/PANEL:" at 11333.46,2937.09 h60
  text "CUT AND TRIM PER M1 BOARD OUTLINE" at 12394.46,2928.87 h60
  text "N.C. ROUTE" at 12394.46,2792.9 h60
  text "X" at 13082.47,2792.9 h60
  text "V. SCORE" at 13260.46,2792.9 h60
  text "CERTIFICATION:" at 11333.46,2663.77 h60
  text "MATERIALS AND WORKMANSHIP FOR ALL PCBS" at 12058.46,2663.77 h60
  text "TO MEET OR EXCEED THE REQUIREMENTS OF:" at 12058.46,2569.71 h60
  text "X" at 11695.97,2441.08 h60
  text "ANSI IPC-A-600F CLASS ->" at 11823.96,2441.08 h60
  text "X" at 13471.97,2441.08 h60
  text "2" at 13581.96,2441.08 h60
  text "1" at 13266.96,2439.58 h60
  text "3" at 13935.96,2439.58 h60
  text "X" at 12507.97,2293.4 h60
  text "RoHS" at 12635.96,2293.4 h60
  text "OTHER" at 13280.37,2293.4 h60
  text "PER ORDER" at 13677.42,2293.4 h60
  text "ALL BOARDS MUST MEET OR EXCEED UL94-V0 REQUIREMENTS." at 11361,2139.57 h60
  text "PCB MUST BEAR THE UL94V-0 UL REGISTERED MATERIAL ID NUMBER" at 11361,2023.5 h60
  text "ADDITIONAL REQUIREMENTS:" at 11333.46,1854.08 h60
  text "MICROSECTION:" at 11408.23,1746.95 h60
  text "YES" at 12313.96,1746.95 h60
  text "REQUIRED" at 13175.46,1602.62 h60
  text "BARE BOARD ELEC. TEST:" at 11408.23,1599.77 h60
  text "NONE" at 12713.96,1599.77 h60
  text "X" at 13057.47,1599.77 h60
  text "PER ORDER" at 13767.46,1599.77 h60
  text "XX MIL VIAS REQUIRE NON-CONDUCTIVE FILL AND PLANARIZE" at 11576.38,1394.82 h59
  text "XX MIL VIAS REQUIRE CONDUCTIVE FILL AND PLANARIZE" at 11584.38,1290.84 h60
  text "OUTER XX MIL TRACES REQUIRE 50 OHM SINGLE-ENDED IMPEDANCE" at 11583.39,1127.46 h58
  text "LAYER 2 & 3 (INNER LAYERS) XX MIL WIDE, XX MIL SPACE / TRACES REQUIRE 100 OHM DIFFERENTIAL IMPEDANCE" at 11575.39,891.75 h60
  text ".Layer_Name" at 577,-858.49 h60
M11 Gerber Information:
  lines w10: -292,-930.17 6308,-930.17 ; -292,-726.83 6310,-726.83 ; -292,-523.5 -292,-1133.5 3713,-1133.5 6310,-1133.5 6310,-523.5 -291.5,-523.5 -291.5,-1133.5 1284,-1133.5 ; 2173,-1133.5 2173,-523.5 ; 3440,-726.83 3440,-523.5 ; 4280,-726.83 4280,-523.5 ; 4902,-1140 4902,-937.17
  text "ALL ARTWORK VIEWED FROM TOP SIDE" at -228.5,-655.67 h60
  text "BOARD #:" at 2248,-655.67 h60
  text ".PRJ_Number" at 2793.5,-655.67 h60
  text "REV:" at 3638,-655.67 h60
  text ".PCB_Rev" at 3929.5,-655.67 h60
  text "SVN REV:" at 4476,-655.67 h60
  text ".VersionControl_RevNumber" at 4982,-655.67 h60
  text "LAYER NAME =" at -228.5,-858.49 h60
  text "TID #:" at 2248,-859 h60
  text ".TID" at 2793.5,-859 h60
  text "PLOT NAME =" at -228.5,-1064.33 h60
  text ".plot_File_Name" at 577,-1064.33 h60
  text "GENERATED    :" at 2250,-1064.33 h60
  text ".Print_Date" at 3119.5,-1064.33 h60
  text ".Print_Time" at 3848.5,-1064.33 h60
  text "TEXAS INSTRUMENTS" at 5113,-1064.33 h60
M12 Stackup:
  drawing of 503 lines, arcs and shapes, not listed
  text "Layer" at 10243.52,8913.55 h60
  text "Name" at 10653.43,8913.55 h60
  text "Material" at 11663.15,8913.55 h60
  text "Thickness" at 12522.92,8913.55 h60
  text "Constant" at 13172.76,8913.55 h60
  text "Board Layer Stack" at 13742.62,8913.55 h60
  text "Top Overlay" at 10653.43,8793.55 h60
  text "Top Solder" at 10653.43,8673.55 h60
  text "Solder Resist" at 11663.15,8673.55 h60
  text "0.40mil" at 12522.92,8673.55 h60
  text "3.3" at 13172.76,8673.55 h60
  text "1" at 10243.52,8553.55 h60
  text "Top Layer" at 10653.43,8553.55 h60
  text "2.80mil" at 12522.92,8553.55 h60
  text "Dielectric 1" at 10653.43,8433.55 h60
  text "FR-4 High Tg" at 11663.15,8433.55 h60
  text "3.00mil" at 12522.92,8433.55 h60
  text "4.2" at 13172.76,8433.55 h60
  text "2" at 10243.52,8313.55 h60
  text "Layer 1 - GND" at 10653.43,8313.55 h60
  text "1.40mil" at 12522.92,8313.55 h60
  text "Dielectric 2" at 10653.43,8193.55 h60
  text "FR-4 High Tg" at 11663.15,8193.55 h60
  text "8.00mil" at 12522.92,8193.55 h60
  text "4.2" at 13172.76,8193.55 h60
  text "3" at 10243.52,8073.55 h60
  text "Signal Layer 2" at 10653.43,8073.55 h60
  text "1.40mil" at 12522.92,8073.55 h60
  text "Dielectric 3" at 10653.43,7953.55 h60
  text "FR-4 High Tg" at 11663.15,7953.55 h60
  text "8.00mil" at 12522.92,7953.55 h60
  text "4.2" at 13172.76,7953.55 h60
  text "4" at 10243.52,7833.55 h60
  text "Layer 3 - GND" at 10653.43,7833.55 h60
  text "1.40mil" at 12522.92,7833.55 h60
  text "Dielectric 4" at 10653.43,7713.55 h60
  text "FR-4 High Tg" at 11663.15,7713.55 h60
  text "9.60mil" at 12522.92,7713.55 h60
  text "4.2" at 13172.76,7713.55 h60
  text "5" at 10243.52,7593.55 h60
  text "Layer 4 - Power" at 10653.43,7593.55 h60
  text "1.40mil" at 12522.92,7593.55 h60
  text "Dielectric 5" at 10653.43,7473.55 h60
  text "FR-4 High Tg" at 11663.15,7473.55 h60
  text "8.00mil" at 12522.92,7473.55 h60
  text "4.2" at 13172.76,7473.55 h60
  text "6" at 10243.52,7353.55 h60
  text "Signal Layer 5" at 10653.43,7353.55 h60
  text "1.40mil" at 12522.92,7353.55 h60
  text "Dielectric 6" at 10653.43,7233.55 h60
  text "FR-4 High Tg" at 11663.15,7233.55 h60
  text "8.00mil" at 12522.92,7233.55 h60
  text "4.2" at 13172.76,7233.55 h60
  text "7" at 10243.52,7113.55 h60
  text "Layer 6 - GND" at 10653.43,7113.55 h60
  text "1.40mil" at 12522.92,7113.55 h60
  text "Dielectric 7" at 10653.43,6993.55 h60
  text "FR-4 High Tg" at 11663.15,6993.55 h60
  text "3.00mil" at 12522.92,6993.55 h60
  text "4.2" at 13172.76,6993.55 h60
  text "8" at 10243.52,6873.55 h60
  text "Bottom Layer" at 10653.43,6873.55 h60
  text "2.80mil" at 12522.92,6873.55 h60
  text "Bottom Solder" at 10653.43,6753.55 h60
  text "Solder Resist" at 11663.15,6753.55 h60
  text "0.40mil" at 12522.92,6753.55 h60
  text "3.3" at 13172.76,6753.55 h60
  text "Bottom Overlay" at 10653.43,6633.55 h60
  text ".Layer_Name" at 577,-858.49 h60
M13 Component Bodies Top:
  text ".Layer_Name" at 577,-858.49 h60
M14 Component Bodies Bottom:
  text ".Layer_Name" at 577,-858.49 h60
M15 Courtyards Top:
  text ".Layer_Name" at 577,-858.49 h60
M16 Courtyards Bottom:
  text ".Layer_Name" at 577,-858.49 h60
Drill Drawing:
  drawing of 152 lines, arcs and shapes, not listed
  text "Symbol" at 11043.38,8502.1 h72
  text "Quantity" at 11343.96,8502.1 h72
  text "Finished Hole Size" at 11676.07,8502.1 h72
  text "Plated" at 12312.71,8502.1 h72
  text "Hole Type" at 12571.93,8502.1 h72
  text "Drill Layer Pair" at 12947.18,8502.1 h72
  text "Hole Tolerance" at 13671.51,8502.1 h72
  text "236" at 11343.96,8377.78 h60
  text "7.87mil (0.200mm)" at 11676.07,8377.78 h60
  text "PTH" at 12312.71,8377.78 h60
  text "Round" at 12571.93,8377.78 h60
  text "Top Layer - Bottom Layer" at 12947.18,8377.78 h60
  text "1" at 11343.96,8253.46 h60
  text "8.00mil (0.203mm)" at 11676.07,8253.46 h60
  text "PTH" at 12312.71,8253.46 h60
  text "Round" at 12571.93,8253.46 h60
  text "Top Layer - Bottom Layer" at 12947.18,8253.46 h60
  text "B" at 11018.09,8243.47 h55.25
  text "686" at 11343.96,8129.14 h60
  text "10.00mil (0.254mm)" at 11676.07,8129.14 h60
  text "PTH" at 12312.71,8129.14 h60
  text "Round" at 12571.93,8129.14 h60
  text "Top Layer - Bottom Layer" at 12947.18,8129.14 h60
  text "6" at 11343.96,8004.82 h60
  text "12.00mil (0.305mm)" at 11676.07,8004.82 h60
  text "PTH" at 12312.71,8004.82 h60
  text "Round" at 12571.93,8004.82 h60
  text "Top Layer - Bottom Layer" at 12947.18,8004.82 h60
  text "1" at 11343.96,7880.5 h60
  text "14.00mil (0.356mm)" at 11676.07,7880.5 h60
  text "PTH" at 12312.71,7880.5 h60
  text "Round" at 12571.93,7880.5 h60
  text "Top Layer - Bottom Layer" at 12947.18,7880.5 h60
  text "A" at 11018.09,7870.51 h55.25
  text "24" at 11343.96,7756.18 h60
  text "15.00mil (0.381mm)" at 11676.07,7756.18 h60
  text "PTH" at 12312.71,7756.18 h60
  text "Round" at 12571.93,7756.18 h60
  text "Top Layer - Bottom Layer" at 12947.18,7756.18 h60
  text "399" at 11343.96,7631.86 h60
  text "16.00mil (0.406mm)" at 11676.07,7631.86 h60
  text "PTH" at 12312.71,7631.86 h60
  text "Round" at 12571.93,7631.86 h60
  text "Top Layer - Bottom Layer" at 12947.18,7631.86 h60
  text "10" at 11343.96,7507.54 h60
  text "19.69mil (0.500mm)" at 11676.07,7507.54 h60
  text "PTH" at 12312.71,7507.54 h60
  text "Round" at 12571.93,7507.54 h60
  text "Top Layer - Bottom Layer" at 12947.18,7507.54 h60
  text "26" at 11343.96,7383.22 h60
  text "28.00mil (0.711mm)" at 11676.07,7383.22 h60
  text "PTH" at 12312.71,7383.22 h60
  text "Round" at 12571.93,7383.22 h60
  text "Top Layer - Bottom Layer" at 12947.18,7383.22 h60
  text "2" at 11343.96,7258.9 h60
  text "31.50mil (0.800mm)" at 11676.07,7258.9 h60
  text "PTH" at 12312.71,7258.9 h60
  text "Round" at 12571.93,7258.9 h60
  text "Top Layer - Bottom Layer" at 12947.18,7258.9 h60
  text "22" at 11343.96,7134.58 h60
  text "32.00mil (0.813mm)" at 11676.07,7134.58 h60
  text "PTH" at 12312.71,7134.58 h60
  text "Round" at 12571.93,7134.58 h60
  text "Top Layer - Bottom Layer" at 12947.18,7134.58 h60
  text "C" at 11018.09,7124.59 h55.25
  text "12" at 11343.96,7010.26 h60
  text "38.00mil (0.965mm)" at 11676.07,7010.26 h60
  text "PTH" at 12312.71,7010.26 h60
  text "Round" at 12571.93,7010.26 h60
  text "Top Layer - Bottom Layer" at 12947.18,7010.26 h60
  text "4" at 11343.96,6885.94 h60
  text "59.06mil (1.500mm)" at 11676.07,6885.94 h60
  text "PTH" at 12312.71,6885.94 h60
  text "Round" at 12571.93,6885.94 h60
  text "Top Layer - Bottom Layer" at 12947.18,6885.94 h60
  text "100" at 11343.96,6761.62 h60
  text "63.00mil (1.600mm)" at 11676.07,6761.62 h60
  text "PTH" at 12312.71,6761.62 h60
  text "Round" at 12571.93,6761.62 h60
  text "Top Layer - Bottom Layer" at 12947.18,6761.62 h60
  text "3" at 11343.96,6637.3 h60
  text "68.00mil (1.727mm)" at 11676.07,6637.3 h60
  text "PTH" at 12312.71,6637.3 h60
  text "Round" at 12571.93,6637.3 h60
  text "Top Layer - Bottom Layer" at 12947.18,6637.3 h60
  text "48" at 11343.96,6512.98 h60
  text "70.87mil (1.800mm)" at 11676.07,6512.98 h60
  text "PTH" at 12312.71,6512.98 h60
  text "Round" at 12571.93,6512.98 h60
  text "Top Layer - Bottom Layer" at 12947.18,6512.98 h60
  text "4" at 11343.96,6388.66 h60
  text "125.98mil (3.200mm)" at 11676.07,6388.66 h60
  text "PTH" at 12312.71,6388.66 h60
  text "Round" at 12571.93,6388.66 h60
  text "Top Layer - Bottom Layer" at 12947.18,6388.66 h60
  text "1584 Total" at 11343.96,6264.34 h60
  text ".Layer_Name" at 577,-858.49 h60
M17 Embedded Cavity:
  text ".Layer_Name" at 577,-858.49 h60
M18 Embedded Assembly:
  text ".Layer_Name" at 577,-858.49 h60
M19 Embedded Keepout:
  text ".Layer_Name" at 577,-858.49 h60

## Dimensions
0,-400 to 1000,-400 on M2 Board Dimensions
0,0 to 0,7000 on M2 Board Dimensions
0,0 to 8500,0 on M2 Board Dimensions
